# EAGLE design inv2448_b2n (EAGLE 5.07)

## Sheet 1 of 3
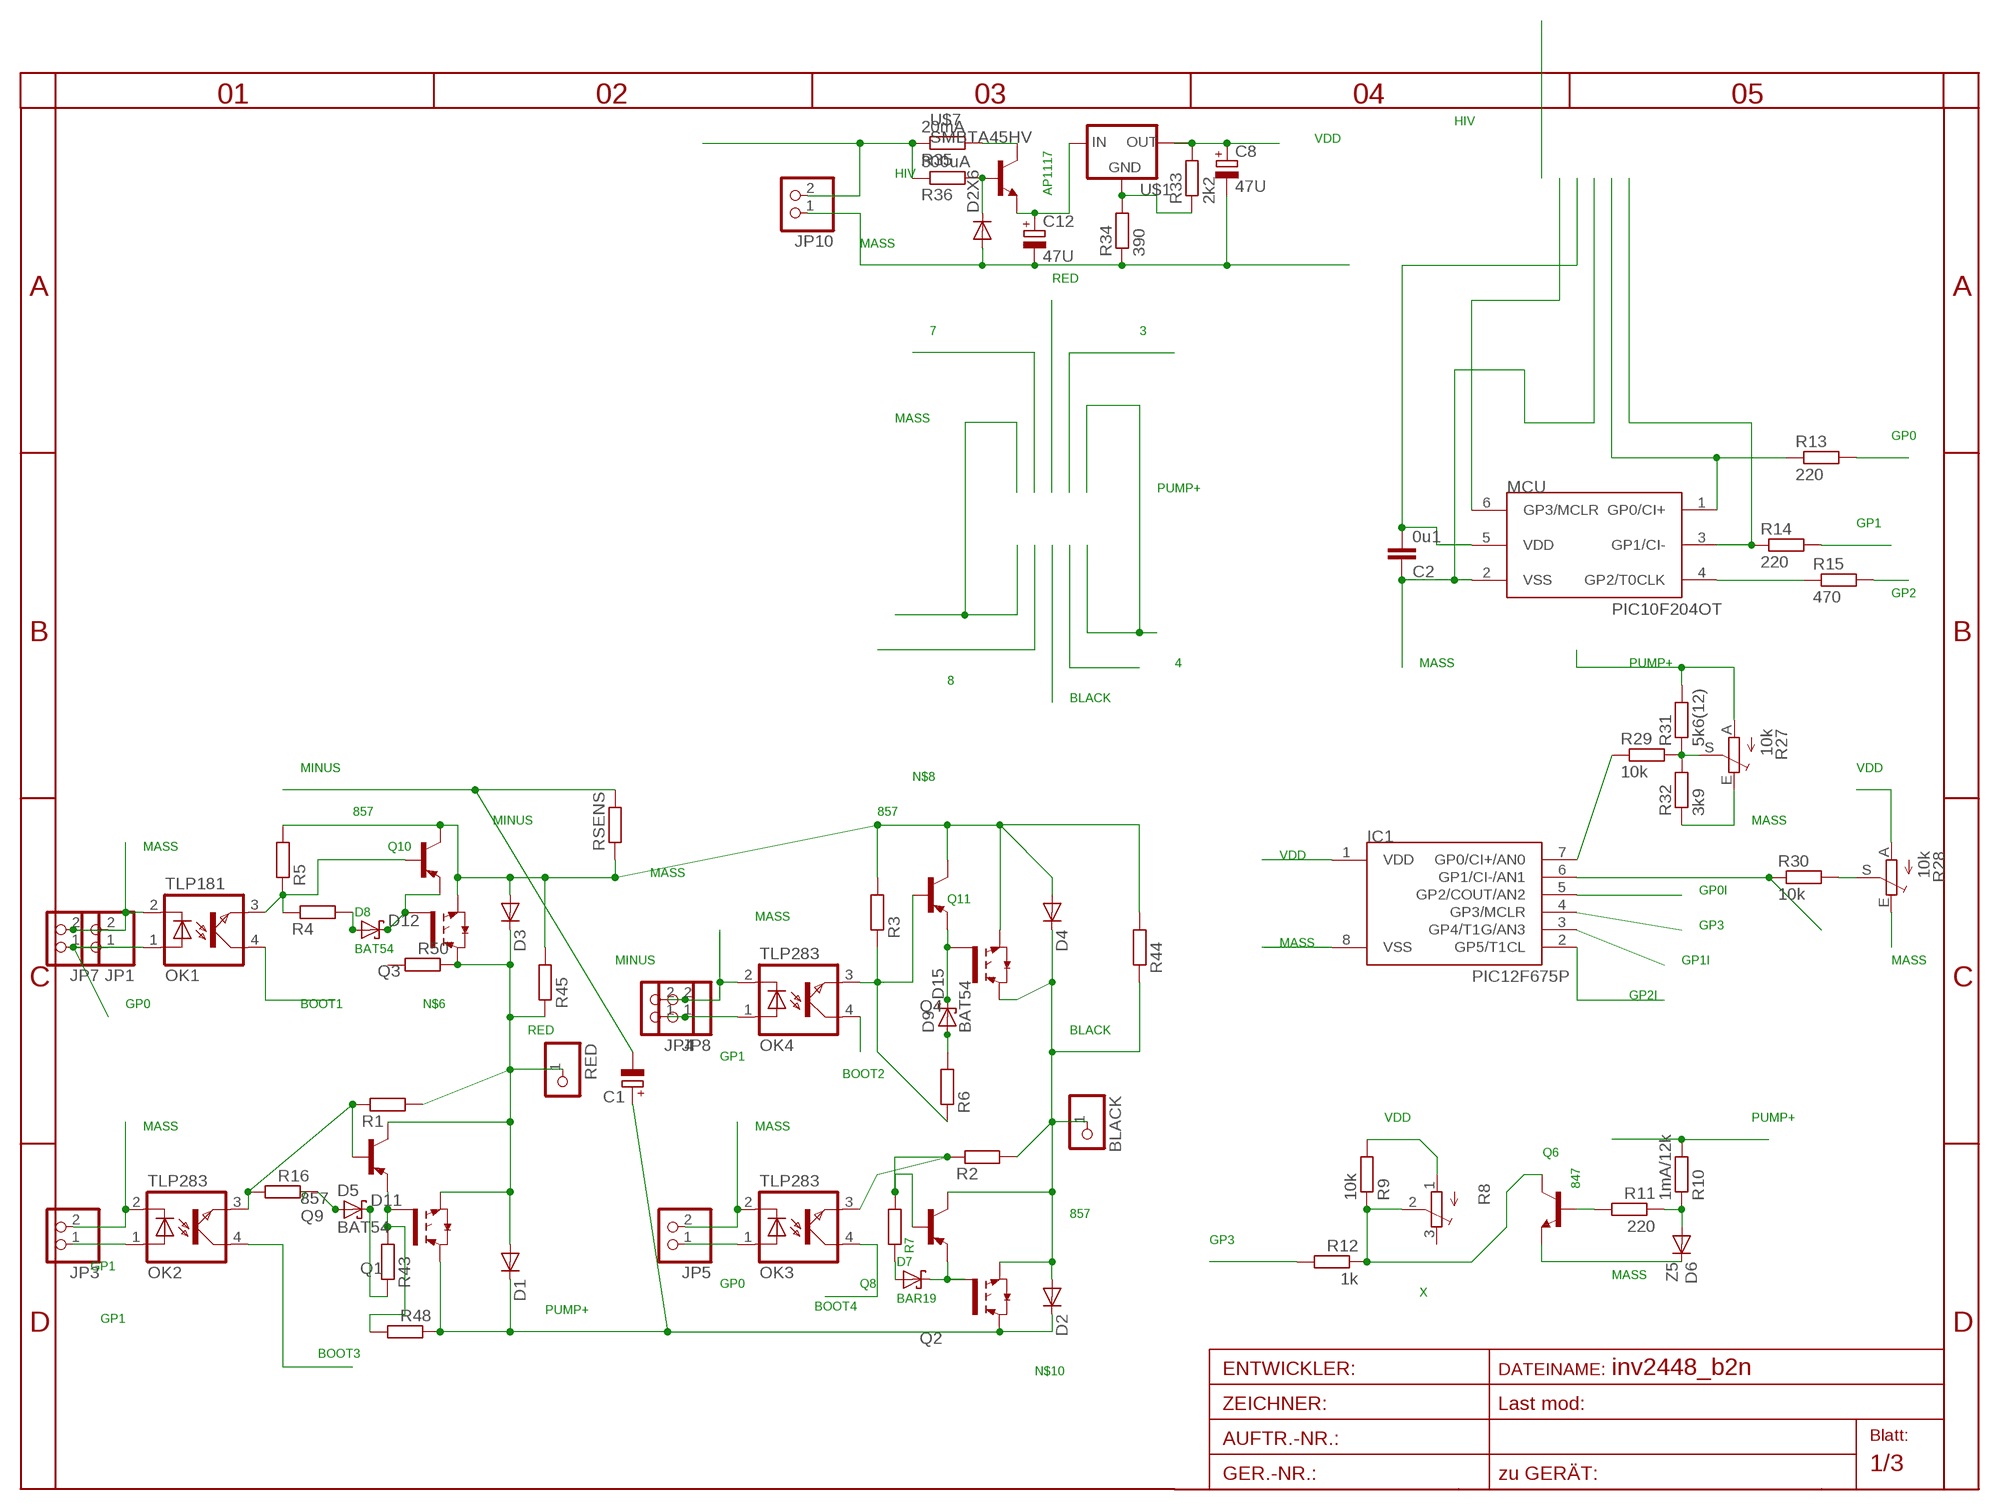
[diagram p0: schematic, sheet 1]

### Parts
BLACK  PINHD-1X14.5MM  [1X4MM5]
C1  CPOL-EUE5-13  [E5-13]
C2  0u1  C-EUC0805  [C0805]
C8  47U  CPOL-EUE  [PANASONIC_E]
C12  47U  CPOL-EUSMCA  [SMC_A]
D1  DIODE-SMC  [SMC]
D2  DIODE-SMC  [SMC]
D2X6  DIODE-MINIMELF  [MINIMELF]
D3  DIODE-SMC  [SMC]
D4  DIODE-SMC  [SMC]
D5  BAT54  [SOT23]
D6  Z5  DIODE-MINIMELF  [MINIMELF]
D7  BAR19  BAT54  [SOT23]
D8  BAT54  [SOT23]
D9  BAT54  [SOT23]
D11  DIODE-MINIMELF  [MINIMELF]
D12  DIODE-MINIMELF  [MINIMELF]
D15  DIODE-MINIMELF  [MINIMELF]
IC1  PIC12F675P  [DIL8]
JP1  PINHD-1X2STR  [1X02]
JP3  PINHD-1X2STR  [1X02]
JP4  PINHD-1X2STR  [1X02]
JP5  PINHD-1X2STR  [1X02]
JP7  PINHD-1X2STR  [1X02]
JP8  PINHD-1X2STR  [1X02]
JP10  PINHD-1X2STR  [1X02]
MCU  PIC10F204OT  [SOT23-6]
OK1  TLP181  TLP283FLAT  [FLAT-4]
OK2  TLP283  TLP283FLAT  [FLAT-4]
OK3  TLP283  TLP283FLAT  [FLAT-4]
OK4  TLP283  TLP283FLAT  [FLAT-4]
Q1  IRG4BC15UD-S  [D2PACK]
Q2  IRG4BC15UD-S  [D2PACK]
Q3  IRG4BC15UD-S  [D2PACK]
Q4  IRG4BC15UD-S  [D2PACK]
Q6  847  BC847ALT1SMD  [SOT23]
Q8  857  BC857ALT1SMD  [SOT23-BEC]
Q9  857  BC857ALT1SMD  [SOT23-BEC]
Q10  857  BC857ALT1SMD  [SOT23-BEC]
Q11  857  BC857ALT1SMD  [SOT23-BEC]
R1  R-EU_R1206  [R1206]
R2  R-EU_R1206  [R1206]
R3  R-EU_R1206  [R1206]
R4  R-EU_R0805  [R0805]
R5  R-EU_R1206  [R1206]
R6  R-EU_R1206  [R1206]
R7  R-EU_R1206  [R1206]
R8  TRIM_EU-3223W  [3223W]
R9  10k  R-EU_R1206  [R1206]
R10  1mA/12k  R-EU_R1206  [R1206]
R11  220  R-EU_R1206  [R1206]
R12  1k  R-EU_0204/7  [0204/7]
R13  220  R-EU_R1206  [R1206]
R14  220  R-EU_0207/10  [0207/10]
R15  470  R-EU_0207/20  [0207/20]
R16  R-EU_R1206  [R1206]
R27  10k  TRIM_EU-RAND160  [RANDL]
R28  10k  TRIM_EU-RAND160  [RANDL]
R29  10k  R-EU_0207/30  [0207/30]
R30  10k  R-EU_R0805  [R0805]
R31  5k6(12)  R-EU_0207/30  [0207/30]
R32  3k9  R-EU_R0805  [R0805]
R33  2k2  R-EU_R0805  [R0805]
R34  390  R-EU_R0805  [R0805]
R35  20mA  R-EU_R1206  [R1206]
R36  300uA  R-EU_R1206  [R1206]
R43  R-EU_0204/2V  [0204V]
R44  R-EU_0204/2V  [0204V]
R45  R-EU_0204/2V  [0204V]
R48  R-EU_R1206  [R1206]
R50  R-EU_R1206  [R1206]
RED  PINHD-1X14.5MM  [1X4MM5]
RSENS  R-EU_CERAM50  [CERAM50]
U$1  AP1117  [SOT223]
U$7  SMBTA45HV  [SOT23HV]

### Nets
3: OK1.3(EMIT) Q10.B R4.1 R5.1
4: OK3.3(EMIT) Q8.B R2.1 R7.2
7: OK2.3(EMIT) Q9.B R1.1 R16.2
BLACK: BLACK.1 D2.A D4.C Q2.3(E) Q4.2(C) Q8.C R2.2 R44.1 ; also sheet 2
BOOT1: OK1.4(COL) ; also sheet 2
BOOT2: OK4.4(COL) ; also sheet 2
BOOT3: OK2.4(COL) ; also sheet 2
BOOT4: OK3.4(COL) ; also sheet 2
GP0: JP1.1 JP5.1 JP7.1 OK1.1(A) OK3.1(A) R13.2
GP0I: IC1.5(GP2/COUT/AN2) MCU.1(GP0/CI+) R13.1
GP1: JP3.1 JP4.1 JP8.1 OK2.1(A) OK4.1(A) R14.2
GP1I: IC1.3(GP4/T1G/AN3) MCU.3(GP1/CI-) R14.1
GP2: R15.2 ; also sheet 2
GP2I: IC1.2(GP5/T1CL) MCU.4(GP2/T0CLK) R15.1
GP3: IC1.4(GP3/MCLR) MCU.6(GP3/MCLR) R12.2
HIV: JP10.2 R35.1 R36.1 ; also sheet 2
MASS: C2.1 C8.- C12.- D2X6.A D3.A D4.A D6.C IC1.8(VSS) JP1.2 JP3.2 JP4.2 JP5.2 JP7.2 JP8.2 JP10.1 MCU.2(VSS) OK1.2(C) OK2.2(C) OK3.2(C) OK4.2(C) Q3.3(E) Q4.3(E) Q6.2(E) Q10.C Q11.C R3.2 R5.2 R27.E R28.E R32.1 R34.1 R44.2 R45.2 RSENS.1 ; also sheet 2
MINUS: C1.- RSENS.2 ; also sheet 2,3
N$2: D8.1(A) D12.A R4.2
N$4: D6.A R10.1 R11.1
N$5: Q6.1(B) R11.2
N$6: D8.3(C) D12.C Q3.1(G) Q10.E
N$7: D9.3(C) D15.C Q4.1(G) Q11.E
N$8: OK4.3(EMIT) Q11.B R3.1 R6.1
N$9: D9.1(A) D15.A R6.2
N$10: D7.3(C) Q2.1(G) Q8.E
N$11: D7.1(A) R7.1
N$12: D5.1(A) D11.A R16.1
N$14: Q1.1(G) Q9.E R43.2 R48.2
N$24: R28.S R30.2
N$30: R33.1 R34.2 U$1.1(GND)
N$31: IC1.6(GP1/CI-/AN1) R30.1
N$32: D2X6.C R36.2 U$7.1(B)
N$33: R35.2 U$7.3(C)
N$34: R27.S R29.2 R31.1 R32.2
N$35: IC1.7(GP0/CI+/AN0) R29.1
N$36: C12.+ U$1.3(IN) U$7.2(E)
N$37: D5.3(C) D11.C R43.1
PUMP+: C1.+ D1.C D2.C Q1.2(C) Q2.2(C) R10.2 R27.A R31.2 R48.1 ; also sheet 2,3
RED: D1.A D3.C Q1.3(E) Q3.2(C) Q9.C R1.2 R45.1 R50.1 RED.1 ; also sheet 2
VDD: C2.2 C8.+ IC1.1(VDD) MCU.5(VDD) R8.1(A) R9.2 R28.A R33.2 U$1.2(OUT) U$1.4(TAB)
X: Q6.3(C) R8.2(S) R9.1 R12.1
Unconnected: R8.3(E) R50.2

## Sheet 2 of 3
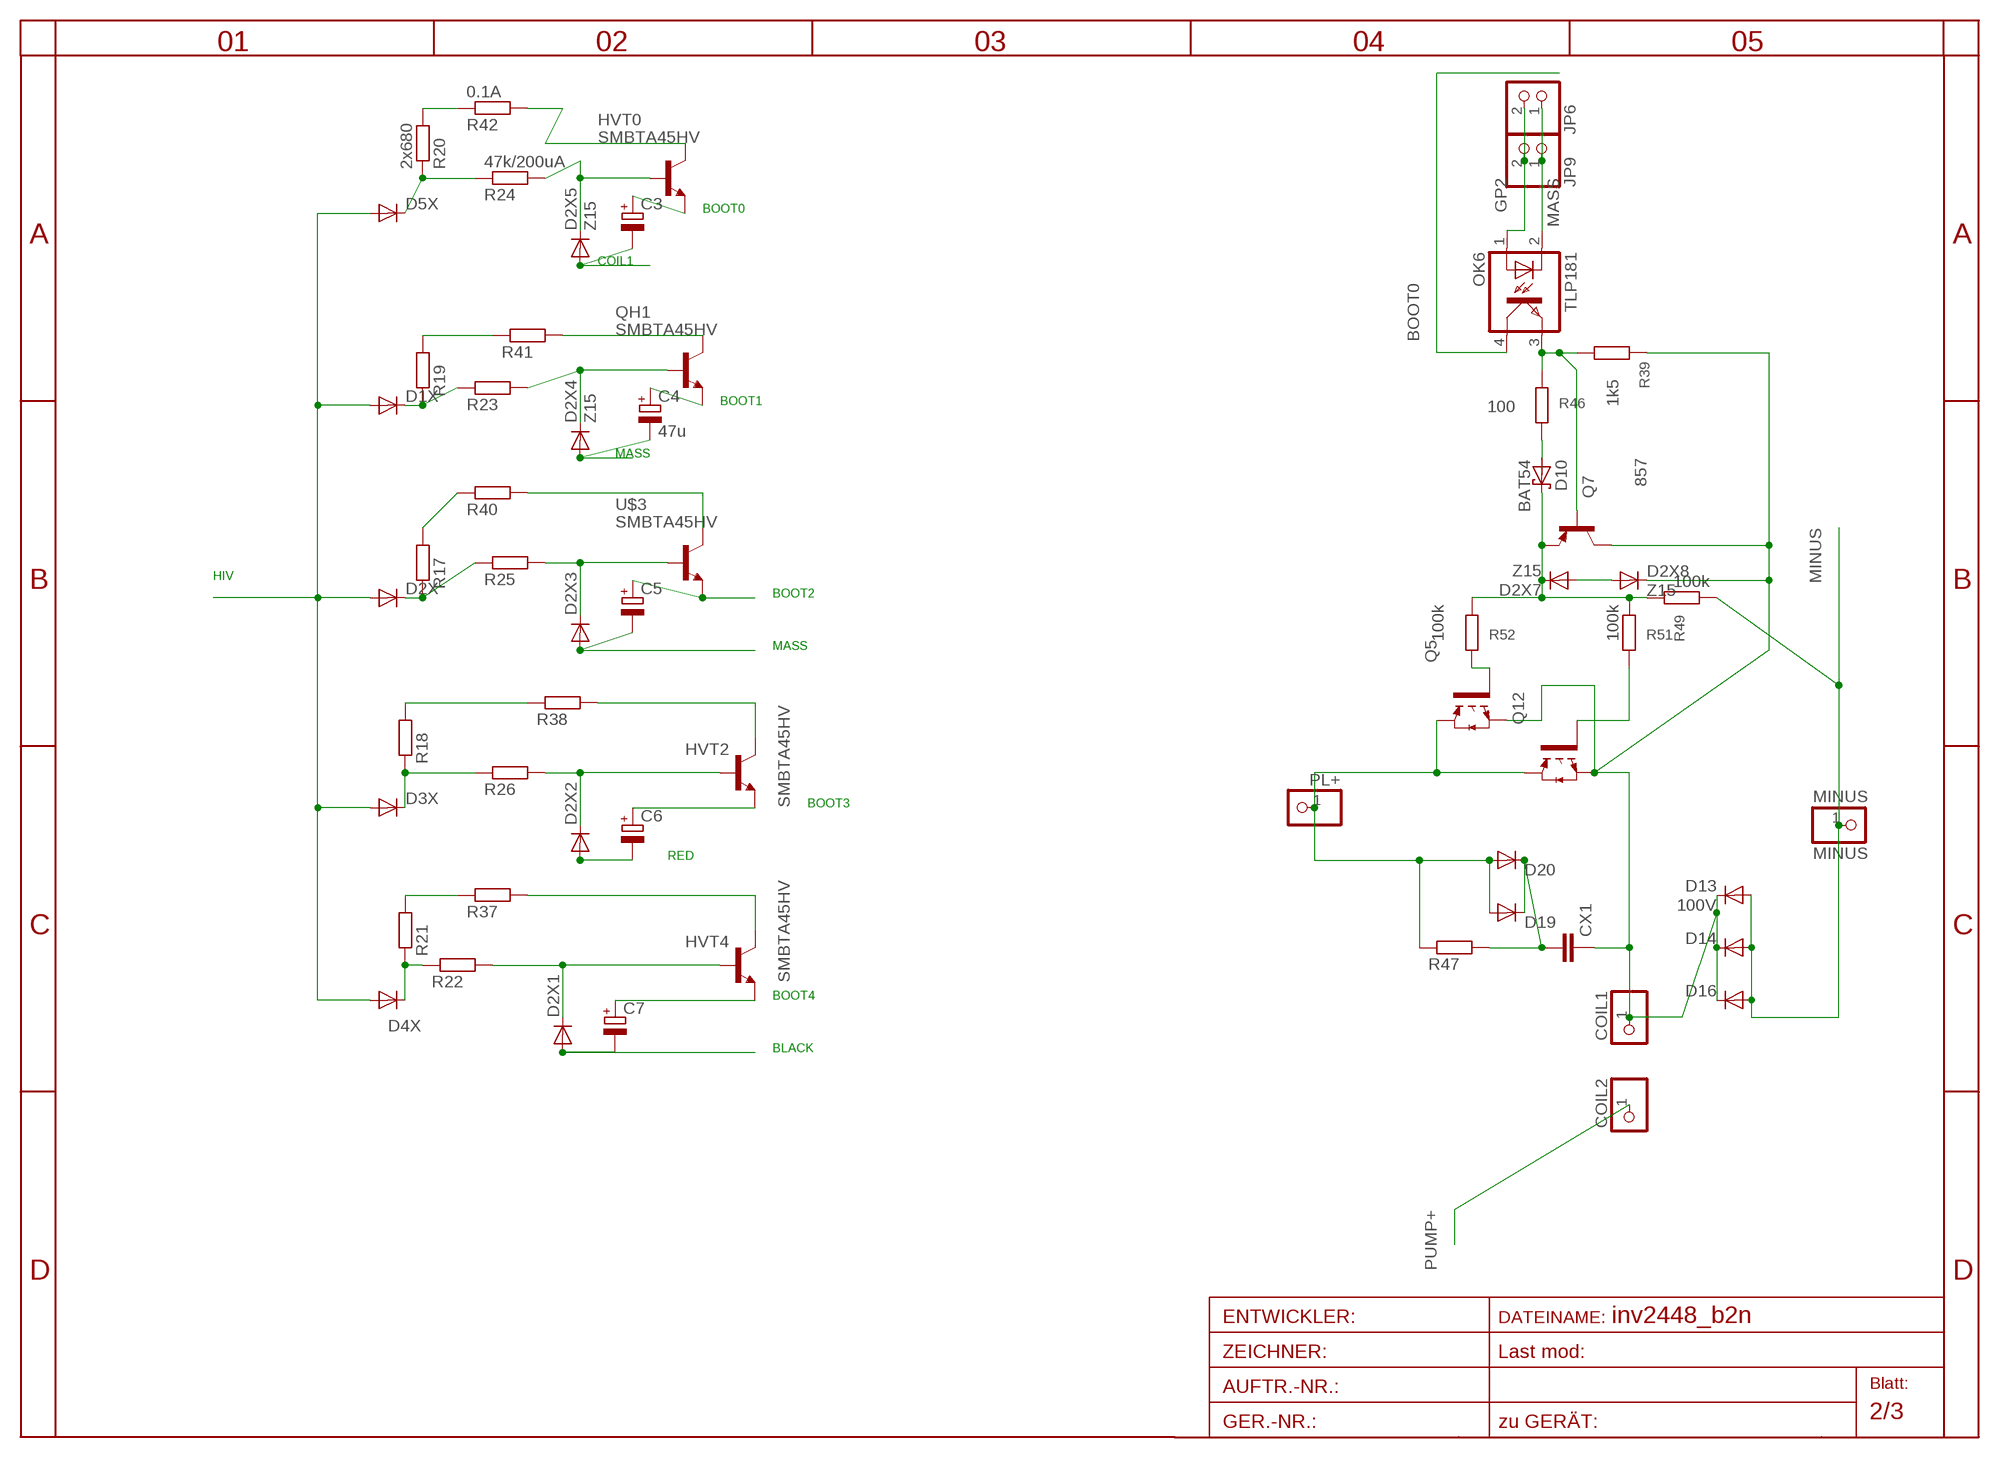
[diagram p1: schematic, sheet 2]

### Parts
C3  CPOL-EUE  [PANASONIC_E]
C4  47u  CPOL-EUE  [PANASONIC_E]
C5  CPOL-EUE  [PANASONIC_E]
C6  CPOL-EUE  [PANASONIC_E]
C7  CPOL-EUE  [PANASONIC_E]
COIL1  PINHD-1X14.5MM  [1X4MM5]
COIL2  PINHD-1X14.5MM  [1X4MM5]
CX1  CXXC22B10  [XC22B10]
D1X  DIODE-SMA-DO214  [SMA-DO214AC]
D2X  DIODE-SMA-DO214  [SMA-DO214AC]
D2X1  DIODE-MINIMELF  [MINIMELF]
D2X2  DIODE-MINIMELF  [MINIMELF]
D2X3  DIODE-MINIMELF  [MINIMELF]
D2X4  Z15  DIODE-MINIMELF  [MINIMELF]
D2X5  Z15  DIODE-MINIMELF  [MINIMELF]
D2X7  Z15  DIODE-MINIMELF  [MINIMELF]
D2X8  Z15  DIODE-MINIMELF  [MINIMELF]
D3X  DIODE-SMA-DO214  [SMA-DO214AC]
D4X  DIODE-SMA-DO214  [SMA-DO214AC]
D5X  DIODE-SMA-DO214  [SMA-DO214AC]
D10  BAT54  [SOT23]
D13  100V  DIODE-SMC  [SMC]
D14  DIODE-SMC  [SMC]
D16  DIODE-SMC  [SMC]
D19  DIODE-SMC  [SMC]
D20  DIODE-SMC  [SMC]
HVT0  SMBTA45HV  [SOT23HV]
HVT2  SMBTA45HV  [SOT23HV]
HVT4  SMBTA45HV  [SOT23HV]
JP6  PINHD-1X2STR  [1X02]
JP9  PINHD-1X2STR  [1X02]
MINUS  MINUS  PINHD-1X14.5MM  [1X4MM5]
OK6  TLP181  TLP283FLAT  [FLAT-4]
PL+  PINHD-1X14.5MM  [1X4MM5]
Q5  IRG4BC15UD-S  [D2PACK]
Q7  857  BC857ALT1SMD  [SOT23-BEC]
Q12  IRG4BC15UD-S  [D2PACK]
QH1  SMBTA45HV  [SOT23HV]
R17  R-EU_R1206  [R1206]
R18  R-EU_R1206  [R1206]
R19  R-EU_R1206  [R1206]
R20  2x680  R-EU_R1206  [R1206]
R21  R-EU_R1206  [R1206]
R22  R-EU_R1206  [R1206]
R23  R-EU_R1206  [R1206]
R24  47k/200uA  R-EU_R1206  [R1206]
R25  R-EU_R1206  [R1206]
R26  R-EU_R1206  [R1206]
R37  R-EU_R1206  [R1206]
R38  R-EU_R1206  [R1206]
R39  1k5  R-EU_R1206  [R1206]
R40  R-EU_R1206  [R1206]
R41  R-EU_R1206  [R1206]
R42  0.1A  R-EU_R1206  [R1206]
R46  100  R-EU_R1206  [R1206]
R47  R-EU_0207/5V  [0207/5V]
R49  100k  R-EU_0207/30  [0207/30]
R51  100k  R-EU_0207/30  [0207/30]
R52  100k  R-EU_0207/30  [0207/30]
U$3  SMBTA45HV  [SOT23HV]

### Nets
BLACK: C7.- D2X1.A ; also sheet 1
BOOT0: C3.+ HVT0.2(E) OK6.4(COL)
BOOT1: C4.+ QH1.2(E) ; also sheet 1
BOOT2: C5.+ U$3.2(E) ; also sheet 1
BOOT3: C6.+ HVT2.2(E) ; also sheet 1
BOOT4: C7.+ HVT4.2(E) ; also sheet 1
COIL1: C3.- COIL1.1 CX1.1 D2X5.A D2X8.C D13.C D14.C D16.C Q5.3(E) Q7.C Q12.3(E) R39.1
GP2: JP6.2 JP9.2 OK6.1(A) ; also sheet 1
HIV: D1X.A D2X.A D3X.A D4X.A D5X.A D19.A D20.A PL+.1 Q5.2(C) Q12.2(C) R47.1 ; also sheet 1
MASS: C4.- C5.- D2X3.A D2X4.A JP6.1 JP9.1 OK6.2(C) ; also sheet 1
MINUS: D13.A D14.A D16.A MINUS.1 R49.1 ; also sheet 1,3
N$1: D2X7.C D10.3(C) Q7.E R49.2 R51.1 R52.1
N$3: D10.1(A) R46.1
N$13: D3X.K(C) R18.1 R26.1
N$15: D4X.K(C) R21.1 R22.1
N$16: D2X.K(C) R17.1 R25.1
N$17: D1X.K(C) R19.1 R23.1
N$18: D5X.K(C) R20.1 R24.1
N$19: D2X1.C HVT4.1(B) R22.2
N$20: D2X5.C HVT0.1(B) R24.2
N$21: D2X4.C QH1.1(B) R23.2
N$22: D2X2.C HVT2.1(B) R26.2
N$23: D2X3.C R25.2 U$3.1(B)
N$25: HVT2.3(C) R38.2
N$26: HVT4.3(C) R37.2
N$27: R40.2 U$3.3(C)
N$28: HVT0.3(C) R42.2
N$29: QH1.3(C) R41.2
N$38: R21.2 R37.1
N$39: R18.2 R38.1
N$40: R17.2 R40.1
N$41: R19.2 R41.1
N$42: R20.2 R42.1
N$43: OK6.3(EMIT) Q7.B R39.2 R46.2
N$44: D2X7.A D2X8.A
N$47: Q5.1(G) R52.2
N$48: Q12.1(G) R51.2
PUMP+: COIL2.1 ; also sheet 1,3
RED: C6.- D2X2.A ; also sheet 1
SNUB: CX1.2 D19.C D20.C R47.2

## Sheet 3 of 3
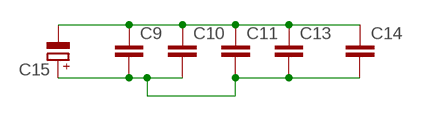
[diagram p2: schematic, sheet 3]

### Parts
C9  C-EUC1206  [C1206]
C10  C-EUC1206  [C1206]
C11  C-EUC1206  [C1206]
C13  C-EUC1206  [C1206]
C14  C-EUC1206  [C1206]
C15  CPOL-EUE2.5-7  [E2,5-7]

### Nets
MINUS: C9.1 C10.1 C11.1 C13.1 C14.1 C15.- ; also sheet 1,2
PUMP+: C9.2 C10.2 C11.2 C13.2 C14.2 C15.+ ; also sheet 1,2

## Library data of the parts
BLACK COIL1 COIL2 MINUS PL+ RED = pinhead:PINHD-1X1: PIN HEADER
C1 C3-C7 C15 = rcl:CPOL-EU: POLARIZED CAPACITOR, European symbol
C2 C9-C11 C13 C14 = rcl:C-EU: CAPACITOR, European symbol
C8 C12 = rcl-2:CPOL-EU: POLARIZED CAPACITOR, European symbol
CX1 = rcl:CX: X CAPACITOR
D1 D1X D2 D2X D2X1-D2X8 D3 D3X D4 D4X D5X D6 D11-D16 D19 D20 = diode:DIODE-: DIODE
D5 D7-D10 = diode:BAT54: Schottky Diodes
HVT0 HVT2 HVT4 QH1 U$3 U$7 = transistor-npn:SMBTA45
IC1 = microchip-5:PIC12F6*: uPC nW 1k Program Flash memory 2x Timer Comparator 10b A/D converter/ 4xIN
JP1 JP3-JP10 = pinhead:PINHD-1X2: PIN HEADER
MCU = microchip-3:PIC10F2*: uPC nW 0,25/0,5k Program Flash memory Comparator
OK1-OK4 OK6 = optocoupler:TLP283: TOSHIBA PHOTOCOUPLER GaAs IRED & PHOTO-TRANSISTOR Source: http://www.semicon.toshiba.co.jp/td/en/Opto/Photocoupler/en_20050928_TLP283_datasheet.pdf
Q1-Q5 Q12 = transistor-power:IRG4BC15UD-: INSULATED GATE BIPOLAR TRANSISTOR WITH ULTRAFAST SOFT RECOVERY DIODE
Q6 = transistor-npn:BC847*: NPN Transistor
Q7-Q11 = transistor-pnp:BC857*: PNP Transistror
R1-R7 R9-R12 R16-R26 R35-R38 R40-R45 R47 R48 R50 RSENS = rcl:R-EU_: RESISTOR, European symbol
R8 R27 R28 = pot:TRIM_EU-: POTENTIOMETER
R13-R15 R29-R34 R39 R46 R49 R51 R52 = rcl-2:R-EU_: RESISTOR, European symbol
U$1 = v-reg:AP1117

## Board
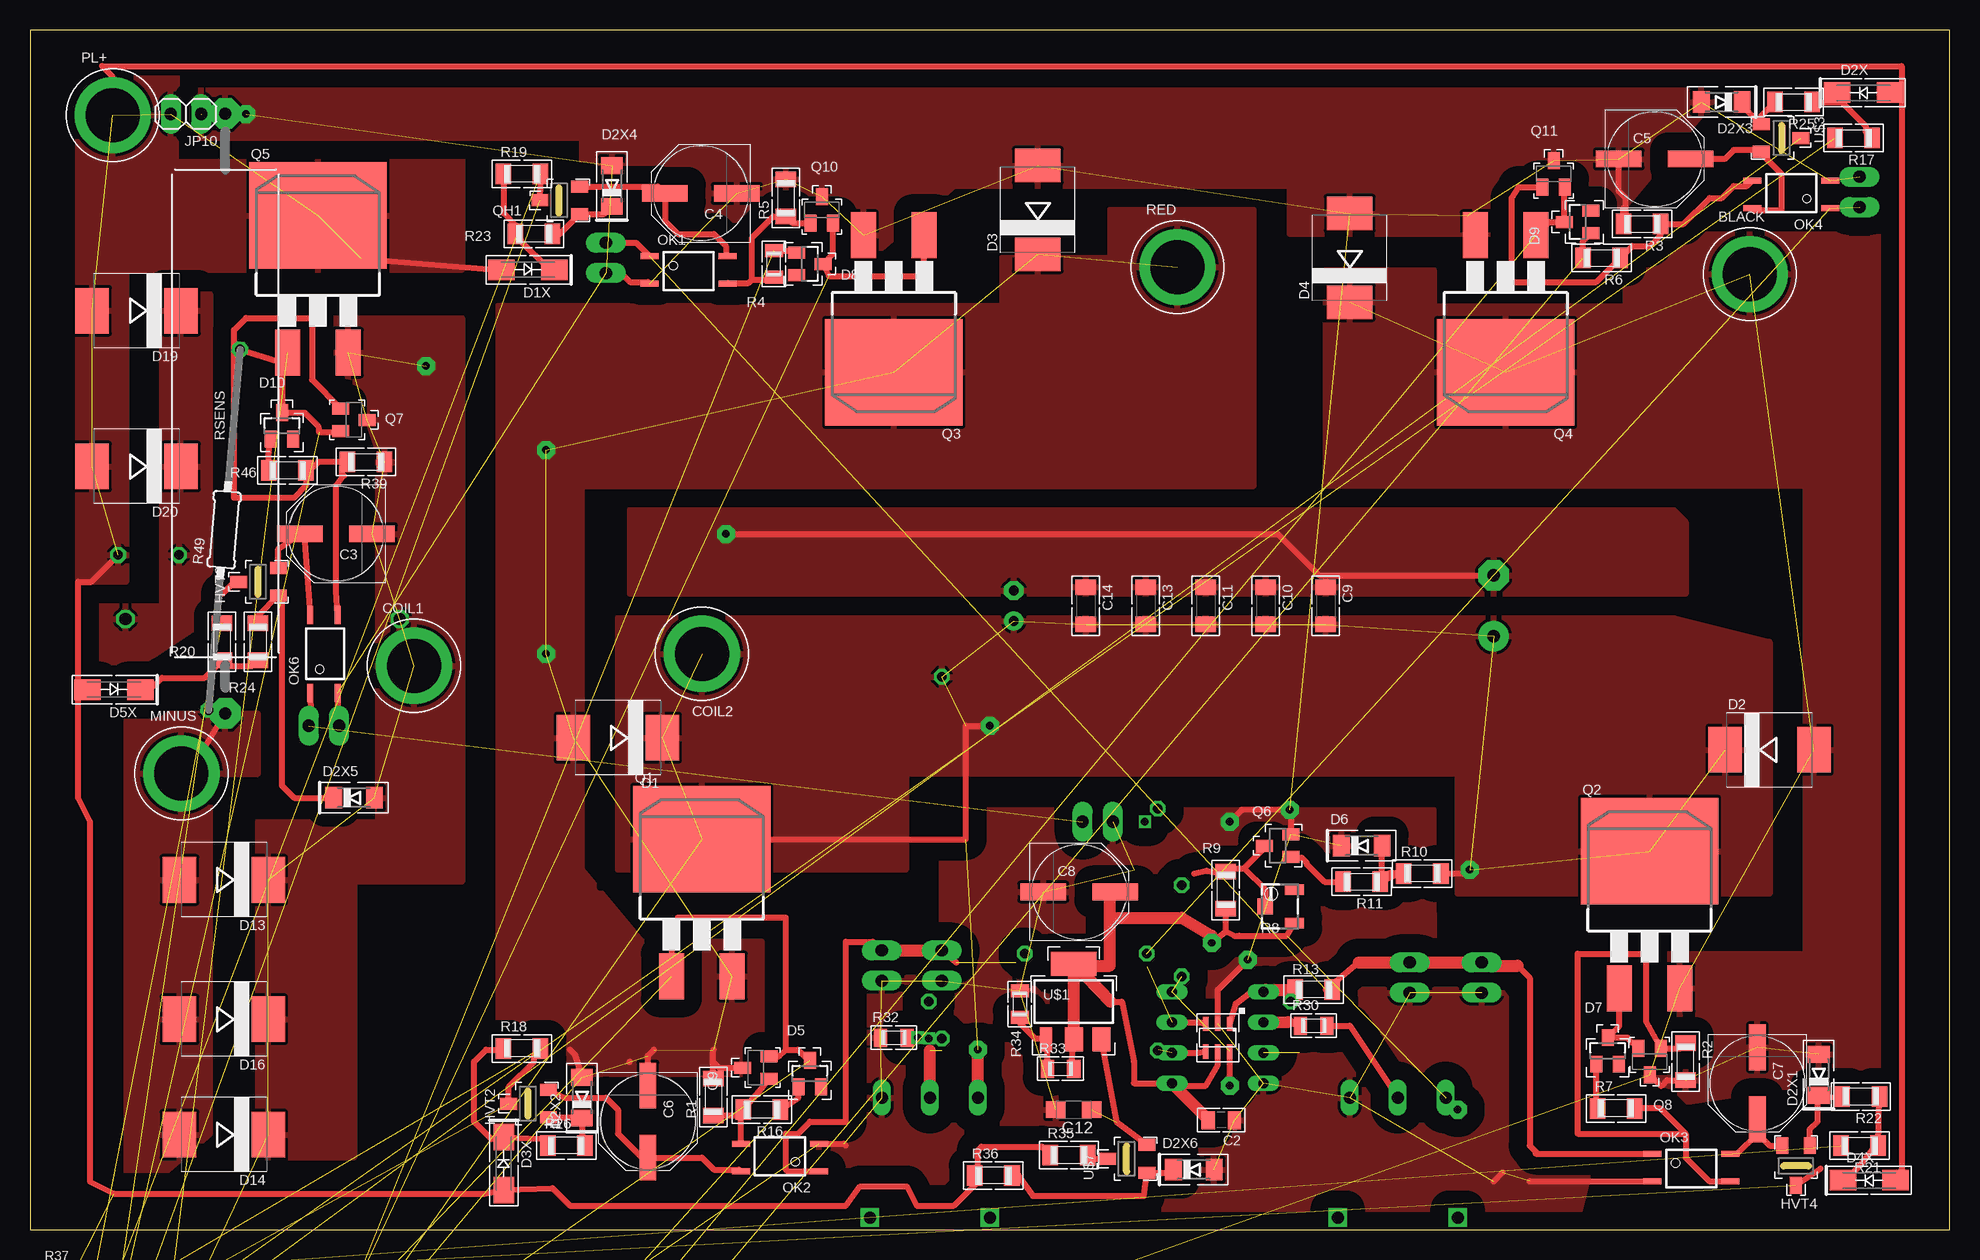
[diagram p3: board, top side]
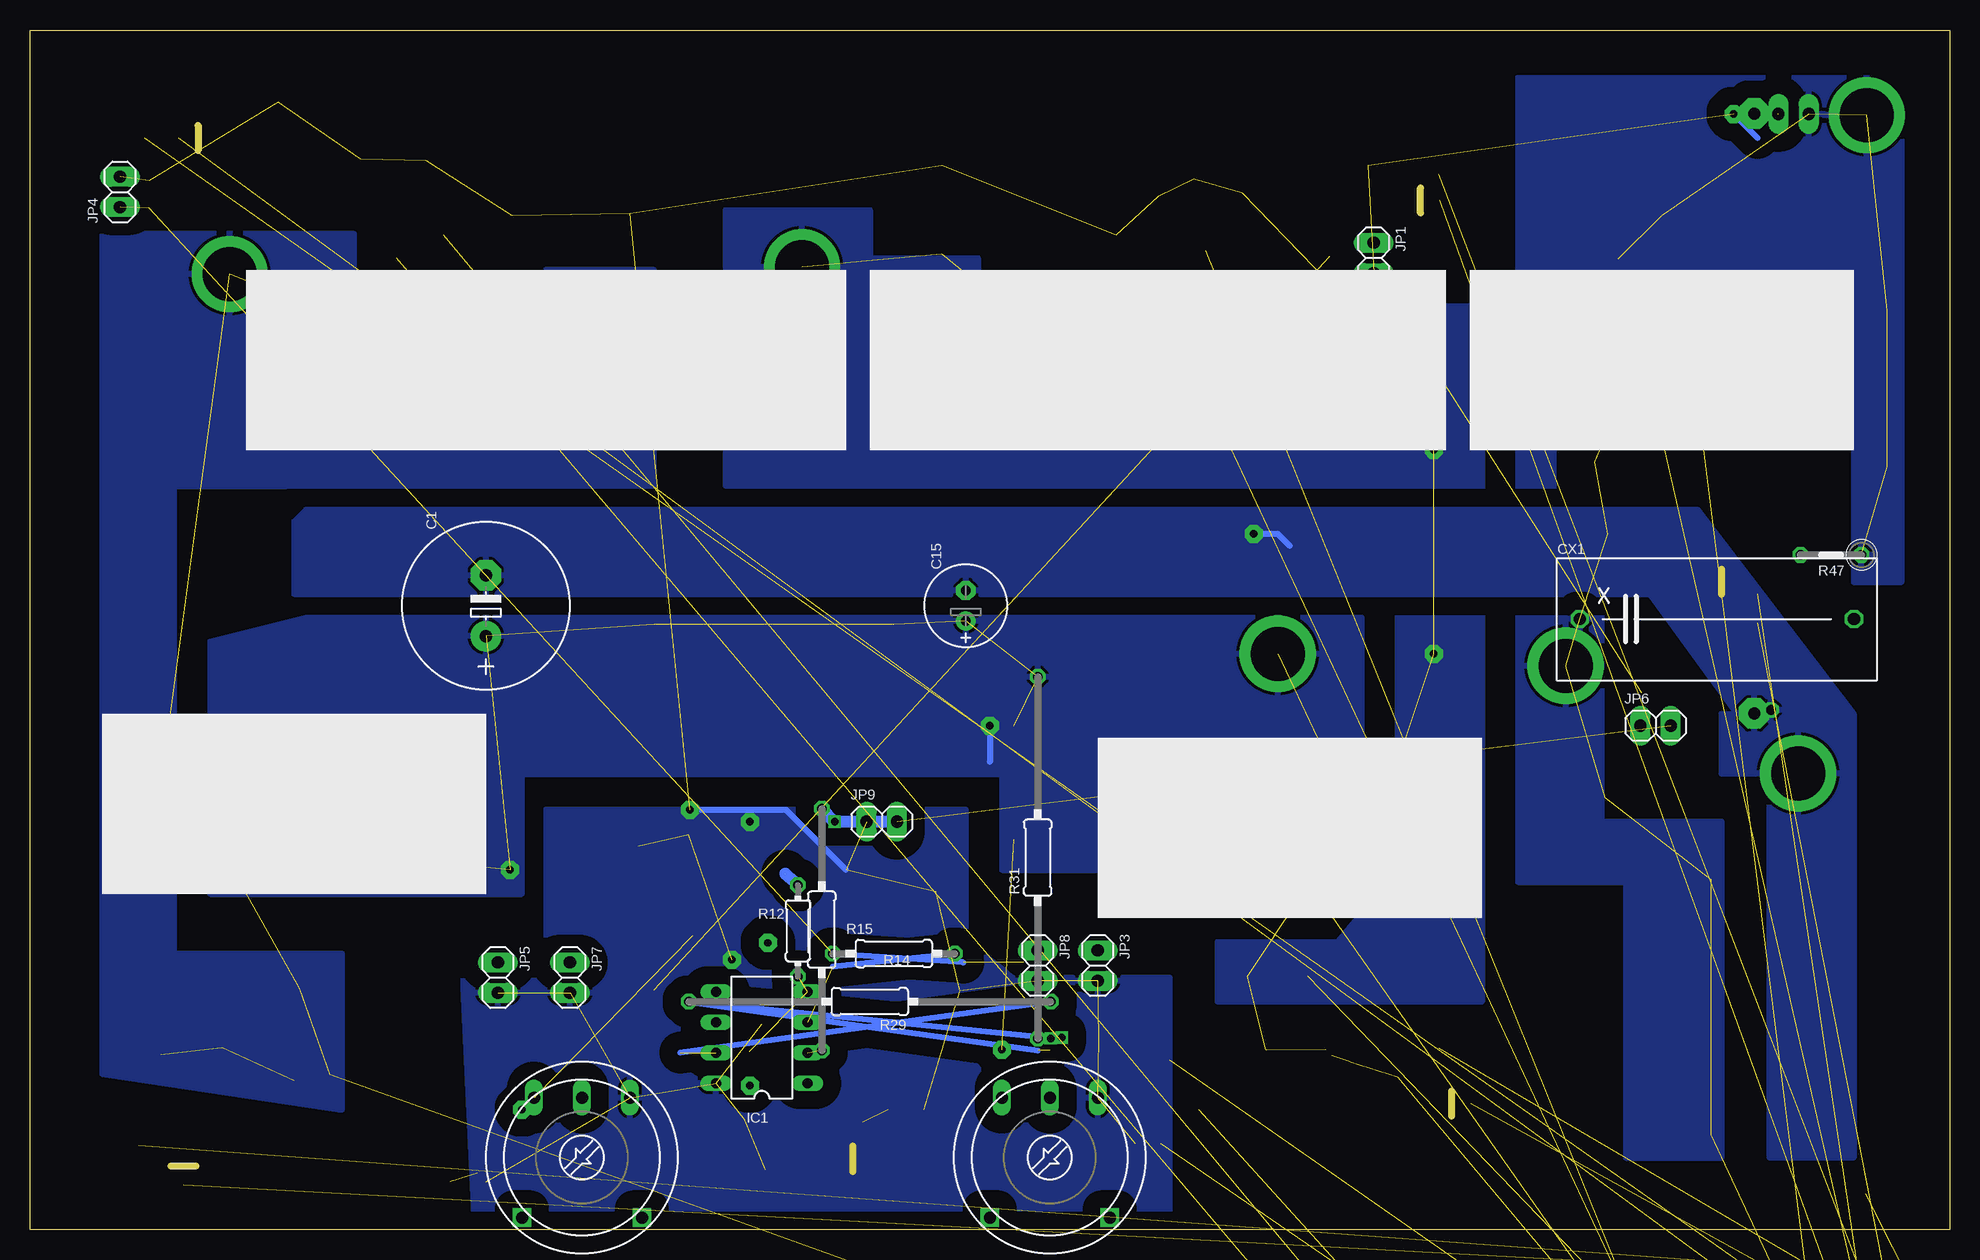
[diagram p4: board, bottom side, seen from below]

Size 160 x 100 mm. Coordinates in mm from the lower left corner, seen from the top.
Outline: 0,0 160,0 160,100 0,100 0,0
Copper layers (1*16): Top 0.035mm / dielectric 1.5mm / Bottom 0.035mm
Design rules "default *": minimum track width 10mil, minimum drill 20mil, track to track 8mil, track to pad 8mil, pad to pad 8mil, via to via 8mil, smd to smd 8mil, copper to edge 40mil, drill to drill 8mil, minimum pad ring 10mil, minimum via ring 8mil, stop-mask expansion 4mil, vias tented up to drill 0mil, thermal gap 10mil

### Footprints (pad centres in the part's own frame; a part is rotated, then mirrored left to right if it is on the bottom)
1X4MM5 = drill 4.5 pad 6.35 round: 1 0,0
E5-13 = drill 1.016 pad 2.54 round: + -2.54,0 | drill 1.016 pad 2.54 octagon: - 2.54,0
C0805 = smd 1.1 x 1.5: 1 -1.1,0; 2 1.1,0
PANASONIC_E = smd 3.8 x 1.4: + 3,0; - -3,0
C1206 = smd 1.3 x 1.7: 1 -1.55,0; 2 1.55,0
SMC_A = smd 1.6 x 1.4: + -1.5,0; - 1.5,0
E2,5-7 = drill 0.813 pad 1.6 round: + -1.27,0 | drill 0.813 pad 1.6 octagon: - 1.27,0
XC22B10 = drill 1.016 octagon: 1 -11.43,0.025; 2 11.43,0.025
SMC = smd 2.8 x 3.8: A 3.7,0; C -3.7,0
SMA-DO214AC = smd 2.2 x 1.7: A 2.2,0; K -2.2,0
MINIMELF = smd 1.4 x 1.8: A 1.7,0; C -1.7,0
SOT23 = smd 1 x 1.4: 1 -0.95,-1.1; 2 0.95,-1.1; 3 0,1.1
SOT23HV = smd 1 x 1.4: 1 -1.15,-1.7; 2 1.15,-1.7; 3 0,1.6
DIL8 = drill 0.8 long: 1 -3.81,-3.81; 2 -1.27,-3.81; 3 1.27,-3.81; 4 3.81,-3.81; 5 3.81,3.81; 6 1.27,3.81; 7 -1.27,3.81; 8 -3.81,3.81
1X02 = drill 1.016 pad 1.676 long: 1 -1.27,0; 2 1.27,0
SOT23-6 = smd 0.45 x 1.2: 1 -1.016,-1.15; 2 0,-1.15; 3 1.016,-1.15; 4 1.016,1.15; 5 0,1.15; 6 -1.016,1.15
FLAT-4 = smd 1.5 x 0.5: 1 -3.25,1.15; 2 -3.25,-1.15; 3 3.25,-1.15; 4 3.25,1.15
D2PACK = smd 2.083 x 3.81: 1 -2.54,-8.89; 3 2.54,-8.89 | smd 11.43 x 8.89: 2 0,2.54
SOT23-BEC = smd 1 x 1.4: B -0.95,-1.1; C 0,1.1; E 0.95,-1.1
R1206 = smd 1.3 x 1.7: 1 -1.55,0; 2 1.55,0
R0805 = smd 1.1 x 1.5: 1 -1.1,0; 2 1.1,0
3223W = smd 0.9 x 1.6: 1 -1.4,-1.215; 3 1.4,-1.215 | smd 1.3 x 1.3: 2 0,1.215
0204/7 = drill 0.813 octagon: 1 -3.81,0; 2 3.81,0
0207/10 = drill 0.813 octagon: 1 -5.08,0; 2 5.08,0
0207/20 = drill 0.813 octagon: 1 -10.08,0; 2 10.08,0
RANDL = drill 1 long: A -4,5; E 4,5; S 0,5 | drill 1 square: P$1 -5,-5; P$2 5,-5
0207/30 = drill 0.813 octagon: 1 -15.08,0; 2 15.08,0
0204V = drill 0.813 octagon: 1 -1.27,0; 2 1.27,0
0207/5V = drill 0.813 octagon: 1 -2.54,0; 2 2.54,0
CERAM50 = drill 1 pad 2.54 octagon: 1 -25,0; 2 25,0
SOT223 = smd 1 x 2: 1 -2.3,-3.15 | smd 1.5 x 2: 2 0,-3.15; 3 2.3,-3.15 | smd 3.8 x 2: 4 0,3.15

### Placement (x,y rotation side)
BLACK  143.35,79.64 0 top
C1  122,52 90 bottom
C2  99.3,9.12 180 top
C3  25.5,58 180 top
C4  55.92,86.38 180 top
C5  135.43,89.25 0 top
C6  51.5,9 270 top
C7  143.98,12.19 270 top
C8  87.46,28.15 0 top
C9  108,52 270 top
C10  103,52 270 top
C11  98,52 270 top
C12  87,10 180 top
C13  93,52 270 top
C14  88,52 270 top
C15  82,52 90 bottom
COIL1  32,47 0 top
COIL2  56,48 180 top
CX1  19.39,50.87 0 bottom
D1  49,41 180 top
D1X  41.5,80 180 top
D2  145,40 0 top
D2X  152.83,94.78 0 top
D2X1  149.1,12.9 90 top
D2X2  46,11 90 top
D2X3  141,94 180 top
D2X4  48.5,87 90 top
D2X5  27,36 0 top
D2X6  97,5 0 top
D2X7  not placed on the board
D2X8  not placed on the board
D3  84,85 90 top
D3X  39.5,5.5 270 top
D4  110,81 90 top
D4X  153.31,4.12 0 top
D5  65,13 0 top
D5X  7,45 180 top
D6  111,32 0 top
D7  131.5,14.9 0 top
D8  65,80.5 270 top
D9  129,84 90 top
D10  21,67 0 top
D11  not placed on the board
D12  not placed on the board
D13  16.16,29.15 180 top
D14  16.16,7.91 180 top
D15  not placed on the board
D16  16.16,17.53 180 top
D19  8.88,76.59 180 top
D20  8.88,63.62 180 top
HVT0  19,54 90 top
HVT2  41.5,10.5 90 top
HVT4  147.2,5.3 180 top
IC1  99,16 90 bottom
JP1  48,81 270 bottom
JP3  71,22 270 bottom
JP4  152.5,86.5 90 bottom
JP5  121,21 270 bottom
JP6  24.5,42 0 bottom
JP7  115,21 270 bottom
JP8  76,22 270 bottom
JP9  89,34 0 bottom
JP10  13,93 180 top
MCU  99,16 180 top
MINUS  12.62,38.02 0 top
OK1  54.9,80 0 top
OK2  62.5,6 180 top
OK3  138.46,5.18 0 top
OK4  146.81,86.29 180 top
OK6  24.5,48 90 top
PL+  6.89,92.9 0 top
Q1  56,30 0 top
Q2  135,29 0 top
Q3  72,74 180 top
Q4  123,74 180 top
Q5  24,82 0 top
Q6  104,32 90 top
Q7  27,67.5 270 top
Q8  135,14 180 top
Q9  60.5,13.5 90 top
Q10  66,85 0 top
Q11  127,88 0 top
Q12  not placed on the board
QH1  44.1,85.8 90 top
R1  56.95,11.05 90 top
R2  138,14 270 top
R3  134.38,83.83 180 top
R4  62,80.5 90 top
R5  63,86 90 top
R6  131,81 180 top
R7  132.2,10.1 0 top
R8  104.18,26.94 90 top
R9  99.67,28.3 270 top
R10  116.05,29.67 0 top
R11  111,29 180 top
R12  96,24.9 270 bottom
R13  107,20 0 top
R14  88,23 180 bottom
R15  94,25 90 bottom
R16  61,10 180 top
R17  152,91 180 top
R18  41,15.1 0 top
R19  41,88 0 top
R20  16,49 90 top
R21  152.5,7 180 top
R22  152.6,11.1 180 top
R23  42,83 0 top
R24  19,49 90 top
R25  147,94 180 top
R26  44.7,7 0 top
R27  75,6 0 bottom
R28  114,6 0 bottom
R29  90,19 180 bottom
R30  107,17 0 top
R31  76,31 90 bottom
R32  72,16 0 top
R33  85.9,13.4 0 top
R34  82.5,18.8 270 top
R35  86.6,6.2 0 top
R36  80.3,4.5 0 top
R37  not placed on the board
R38  not placed on the board
R39  28,64 180 top
R40  not placed on the board
R41  not placed on the board
R42  not placed on the board
R43  not placed on the board
R44  not placed on the board
R45  not placed on the board
R46  21.46,63.28 0 top
R47  9.88,56.24 180 bottom
R48  not placed on the board
R49  16.19,58.34 85 top
R50  not placed on the board
R51  not placed on the board
R52  not placed on the board
RED  95.65,80.23 0 top
RSENS  16.29,68.04 270 top
U$1  87,19 0 top
U$3  146,91 270 top
U$7  91.4,5.9 90 top

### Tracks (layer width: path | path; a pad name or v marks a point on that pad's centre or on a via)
3
  Top 0.5: 60.2,79.2 60.2,82.7 61.95,84.45 R5.1 63.55,83.9 Q10.B | 60.2,79.2 59.9,78.9 58.2,78.9 OK1.3 | 60.2,79.2 61.8,79.2 R4.1
4
  Top 0.5: OK3.3 139.97,4.03 138,6 138,8 | 138,8 129,8 129,23 134.7,23 134.7,17.35 Q8.B 137.55,15.1 R2.1 | R7.2 135.9,10.1 138,8
7
  Top 0.5: OK2.3 59.25,9.6 R16.2 | R16.2 58.75,9.5 R1.1 | Q9.B 60.8,11.55 R16.2
BLACK  (8 unrouted)
  Top 0.5: R2.2 136.45,12.45 136,12 135.9,12 Q8.C
  pour Top (isolate 1.5, rank 2): 108,80 117,80 117,77 133,77 133,83 154,83 154,13 134,10 134,23 148,23 148,62 108,62
  pour Bottom (isolate 1.5, rank 2): 108,80 117,80 117,77 133,77 133,83 154,83 154,13 134,10 134,23 148,23 148,62 108,62
BOOT0
  Top 0.5: OK6.4 22.85,57.86 C3.+ 20.7,56.73 HVT0.2
BOOT1
  Top 0.5: OK1.4 58,81.3 58,82 57,83 54,83 52.92,84.08 C4.+ 52.35,86.95 QH1.2
BOOT2
  Top 0.5: C5.+ 141.25,89.25 142,90 144.15,90 U$3.2 144.3,89.7 146,88 146,85 143.7,85 OK4.4
BOOT3
  Top 0.5: HVT2.2 44.55,11 48,11 49,10 49,8 51,6 C6.+ 56,6 57,5 59.1,5 OK2.4
BOOT4
  Top 0.5: OK3.4 142.33,6.33 144,8 | 144,8 144,9.17 C7.+ | HVT4.2 145,7 144,8
COIL1  (via drill 0.6 pad 1.5)  (12 unrouted)
  other vias: 33,72
  pour Top (isolate 1.5, rank 2): 22,76 36,76 36,29 27,29 27,6 19,6 19,34 29,34 29,54 29,65 27,71 22,72
  pour Bottom (isolate 1.5, rank 2): 26,76 36,76 36,29 27,29 27,6 19,6 19,34 29,34 29,54 33,54 33,65 26,72
GP0  (1 unrouted)
  Top 0.5: R13.2 108,20 110.73,22.27 | 125.5,6.5 125,7 125,21 124,22 | 125.5,6.5 125.58,6.42 | JP5.1 121.27,22 | OK3.1 125.5,6.33 125.5,6.5 | JP1.1 50.53,82.27 OK1.1
  Top 1: 110.73,22.27 JP7.1 JP5.1 | 121.27,22 124,22
GP0I
  Top 0.5: MCU.1 100.52,18.82 102,20 102.62,20 IC1.5 103,20
  Top 1: 103,20 R13.1
GP1  (3 unrouted)
  Top 0.5: JP8.1 77.19,22.27 | OK2.1 63.15,4.85 63,5 63,8 64,8 65,9 68,9 68,24 70.27,24 JP3.1
  Top 1: JP3.1 JP8.1
  Bottom 0.5: 82.19,22.27 R14.2
GP1I  (1 unrouted)
  Top 0.5: IC1.3 97.6,17.27 MCU.3
  Bottom 0.5: R14.1 93.1,21.9
GP2  (via drill 0.6)  (1 unrouted)
  Top 0.5: JP6.2 23.43,43.53 OK6.1
  Bottom 1: JP9.2 v92.92,34 R15.2
GP2I  (1 unrouted)
  Top 0.5: IC1.2 97.36,14.73 MCU.4
  Bottom 0.5: R15.1 94.08,15
GP3  (via drill 0.6 pad 1.5)  (2 unrouted)
  Top 0.5: MCU.6 100.02,13.98 v100,12
  Bottom 0.5: R12.2 96.2,21.2
HIV  (7 unrouted)
  Top 0.5: D4X.A 155.44,4.44 156,5 156,95 | 156,95 156,97 6,97 6.89,96.11 PL+.1 | 4,45 4,36 5,34 5,4 7,3 28.2,3 37.87,2.97 D3X.A 43.55,3.45 45,2 68,2 69.2,3.6 73.1,3.6 73.9,2 77,2 79,4 79,4.25 | 4,45 4,54 5.1,54 R47.1 | 27.62,80.92 D1X.A | D5X.A 4.13,45.13 4,45 | D2X.A 155.65,94.65 156,95 | 79,4.25 R36.1 | 79,4.25 79,6.6 79.3,6.9 84.35,6.9 R35.1
  pour Top (isolate 1.5, rank 2): 4,96 36,96 36,80 8,80 8,54 4,54
  pour Bottom (isolate 1.5, rank 2): 4,96 36,96 36,80 8,80 8,54 4,54
MASS  (via drill 0.6 pad 1.5)  (38 unrouted)
  Top 0.5: Q4.3 119.83,84.52 | MCU.2 99,20 v101.5,22.5 | Q6.2 105.1,34.9 v105,35 101,35 v100,34 | 122.75,4.75 122,4 | v18,93 14.33,93 RSENS.1 | OK3.2 125,4.03 125,4 | JP1.2 49.27,79.73 50,79 51.5,79 OK1.2 | OK2.2 67.85,7.15 68,7 | JP6.1 25.67,43.53 OK6.2 | 132.83,85.17 R3.2 133,84 133,86 132.43,86.57 C5.-
  Bottom 0.5: v105,35 97,35 92,30 | v18,93 16,91
  pour Top (isolate 1.5): 14,95 141,95 131,83 105,83 105,87 77,87 70,81 52,81 48,82 48,87 46,87 46,91 14,91
  pour Top (isolate 1.5, rank 3): 76,35 117,35 117,22 121,22 131,9 129,1 64,1 64,21 74,24 76,24
  pour Bottom (isolate 1.5, rank 3): 82,35 117,35 117,22 124,22 123,1 65,1 65,21 78,21 82,24
MINUS  (via drill 0.6 pad 1.5)
  Top 0.5: C1.- 107.46,54.54 104,58 v58,58 | MINUS.1 14.29,39.69 RSENS.2 16.29,42.9 R49.1
  Bottom 0.5: v58,58 56,58 55,57
  pour Top (isolate 1.5): 138,53 50,53 50,60 137,60 138,59
  pour Top (isolate 1.5, rank 3): 8,43 8,2 15,8 15,38 19,38 19,43
  pour Bottom (isolate 1.5): 8,43 21,60 60,60 60,53 25,53 17,42 9,42
  pour Bottom (isolate 1.5): 138,53 50,53 50,60 137,60 138,59
  pour Bottom (isolate 1.5, rank 3): 8,43 8,6 15,6 15,38 19,38 19,43
N$1  (3 unrouted)
  Top 0.5: R49.2 20.71,72.36 21,72.08 D10.3 22.9,68.1 24,67 24.1,66.5 25.95,66.5 Q7.E
N$2  (1 unrouted)
  Top 0.5: R4.2 63.75,81.6 D8.1
N$3
  Top 0.5: R46.1 19.91,64.76 D10.1
N$4
  Top 0.5: R10.1 113.22,29.67 114.28,29.73 | R11.1 114.28,29.73 | D6.A 112.7,29.3 114.28,29.73
N$5
  Top 0.5: R11.2 107.9,29 106.4,30.5 106.4,30.6 106,31 105.15,31 Q6.1
N$6  (1 unrouted)
  Top 0.5: Q3.1 74.54,80.54 74,79.5 66.6,79.5 D8.3 66.95,81.35 Q10.E
N$7  (1 unrouted)
  Top 0.5: Q4.1 126.65,84 D9.3 127.9,86.85 Q11.E
N$8
  Top 0.5: Q11.B 124.1,86.9 123.5,86 123.5,79 130.55,79 R6.1 133.55,82 135,82 135.93,82.93 R3.1 137.83,83.83 140,86 141,86 142,87 143.12,87 OK4.3
N$9  (1 unrouted)
  Top 0.5: R6.2 129.45,82.4 D9.1
N$10
  Top 0.5: Q2.1 132.46,16.96 D7.3 133.15,16 Q8.E
N$11
  Top 0.5: D7.1 130.55,10.2 R7.1
N$12  (1 unrouted)
  Top 0.5: R16.1 64.05,11 D5.1
N$13
  Top 0.5: R26.1 42.6,7.55 D3X.K 38.45,7.55 37,9 37,14 38,15 39.35,15 R18.1
N$14  (2 unrouted)
  Top 0.5: Q1.1 53.46,25.46 54,26 63,26 63,15 | 64.9,14.1 64,15 63,15 | Q9.E 62.45,14.45 63,15
N$15
  Top 0.5: D4X.K 151.06,3.86 152.6,5.4 153.9,7.05 R21.1 R22.1
N$16
  Top 0.5: R25.1 150.43,94 | 150.43,94 D2X.K | 150.43,94 151,94 153,92 153,91.55 R17.1
N$17
  Top 0.5: D1X.K 43.17,80.13 40.9,82.4 40.9,82.55 R23.1 40.45,83.75 39.5,84.7 39.5,87.95 R19.1
N$18
  Top 0.5: D5X.K 10.13,45.13 11,46 14.55,46 R20.1 16,47 18.55,47 R24.1
N$19
  Top 0.5: R22.2 149.3,11 D2X1.C 149,11.1 149,9 148.35,8.35 HVT4.1
N$20
  Top 0.5: D2X5.C 22,36 21,37 21,52.55 HVT0.1 19,51.15 R24.2
N$21
  Top 0.5: R23.2 44.15,83 QH1.1 47.85,84.65 D2X4.C
N$22
  Top 0.5: HVT2.1 45.95,9.35 D2X2.C 46,6.55 R26.2
N$23
  Top 0.5: D2X3.C 142.7,93.75 U$3.1 144.3,92.85 R25.2
N$24
  Top 0.5: R28.S 110,17 R30.2
N$25  (1 unrouted)
  Top 0.5: HVT2.3 39.9,11.9 42,14 42,14.55
N$26  (1 unrouted)
  Top 0.5: HVT4.3 149.25,5.1
N$27  (1 unrouted)
N$28  (1 unrouted)
  Top 0.5: HVT0.3 17,54 16,53
N$29  (1 unrouted)
  Top 0.5: QH1.3 42.55,87.15
N$30
  Top 0.5: R33.1 84.8,15.75 U$1.1 84.65,15.9 83.8,15.9 82.5,17.2 R34.2
N$31
  Top 0.5: 104.88,17.3 R30.1
  Top 1: IC1.6 104.88,17.3
N$32
  Top 0.5: R36.2 82.4,4.5 83.6,2.8 92.85,2.8 U$7.1 95.05,4.75 D2X6.C
N$33
  Top 0.5: U$7.3 88.45,5.9 R35.2
N$34  (via drill 0.6)  (1 unrouted)
  Top 0.5: R32.2 v74,16
  Top 1: R27.S 75,14.92
  Bottom 0.5: 76,14.92 R29.2 v74.92,15.92 R31.1 v74,16
N$35  (1 unrouted)
  Bottom 0.5: R29.1 105.81,14.73
N$36  (1 unrouted)
  Top 0.5: U$7.2 90.6,8.95 U$1.3
N$37  (2 unrouted)
N$38  (1 unrouted)
N$39  (1 unrouted)
N$40  (1 unrouted)
N$41  (1 unrouted)
N$42  (1 unrouted)
N$43
  Top 0.5: 23.01,63.01 R46.2 | Q7.B 23.5,70.85 23.5,76 18,76 17,75 17,61 22,61 23.01,62.01 23.01,63.01 | OK6.3 25.5,53.25 25.5,62 26.15,62.85 26,63 26,63.55 R39.2 24,64 23.01,63.01
N$44  (1 unrouted)
N$47  (1 unrouted)
N$48  (1 unrouted)
PUMP+  (via drill 0.6 pad 1.5)  (15 unrouted)
  Top 0.5: R10.2 119.67,29.67 v120,30 | Q1.2 78,32.54 78,42 v80,42
  Top 1: R27.A v79,15
  Bottom 0.5: v80,42 80,39
  pour Top (isolate 1.5): 145,49 145,28 119,28 119,38 73,38 73,30 49,30 49,51 137,51
  pour Bottom (isolate 1.5): 145,49 145,28 119,28 119,38 79,38 79,30 49,30 49,51 137,51
RED  (via drill 0.6 pad 1.5)  (12 unrouted)
  Top 0.5: 50,14 49.95,13.95 | D2X2.A 45.4,14.6 45,15 | C6.- 51.5,14.5 52,15 | R1.2 56.95,14 | 56.95,14 56.95,14.95 57,15 | Q9.C 57.45,13.5 56.95,14
  other vias: 43,65 43,48
  pour Top (isolate 1.5, rank 2): 102,62 102,85 90,85 90,81 81,81 81,77 39,77 39,13 64,13 61,24 51,24 46,30 46,62
  pour Bottom (isolate 1.5, rank 2): 102,62 102,85 90,85 90,81 81,81 81,77 39,77 39,19 61,19 61,24 51,24 46,30 46,62
SNUB
  pour Top (isolate 1.5, rank 2): 11,78 15,78 15,51 9,47 5,47 5,52 11,52
VDD  (via drill 0.6 pad 1.5)  (1 unrouted)
  Top 0.5: MCU.5 99,13.7 98,12 95.38,12 IC1.1 92,12.19 92,14 91,19 90.06,18.99 | v119,10 R28.A | 99.67,24.87 R9.2 | 99.67,24.87 v98.5,23.9 98.5,24.5 | 99.67,24.87 100.43,24.47 100.8,24.5 104.75,24.5 R8.1 | 98.2,9.18 C2.2 | R33.2 86.8,13.8 U$1.2 | U$1.4 87,22
  Top 1: IC1.1 98.2,9.18 | 98.5,24.5 96,26 90,26 | U$1.2 U$1.4 90.06,18.99 | 87,22 90,22 90,26 | 90,26 90,27.61 C8.+
X  (1 unrouted)
  Top 0.5: R8.2 102.97,28.34 101.2,30.1 | 101.2,30.1 99.92,30.1 R9.1 99.52,29.7 98.1,29.9 97.05,29.65 | Q6.3 102.9,31.8 101.2,30.1
  Bottom 1: R12.1 97.05,29.65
